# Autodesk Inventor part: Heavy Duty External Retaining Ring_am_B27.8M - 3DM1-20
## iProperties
Shininess: 64.0
Length Units: 11269
Angle Units: 11279
Time Units: 11290
Mass Units: 11283
Length Display Precision: 3
Angle Display Precision: 2
Compacted: True
Part Number: Heavy Duty External Retaining Ring_am_B27.8M - 3DM1-20
Document SubType Name: Modeling
Created: 2006-11
Material: Par défaut
Designer: profs_sti
Density: 0.0
Volumn: 0.0
Area: 0.0
PropertySet Name: Model Information
Control State: 0
Master: False
Checked Out: False
Author: profs_sti
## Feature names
1. Base1
